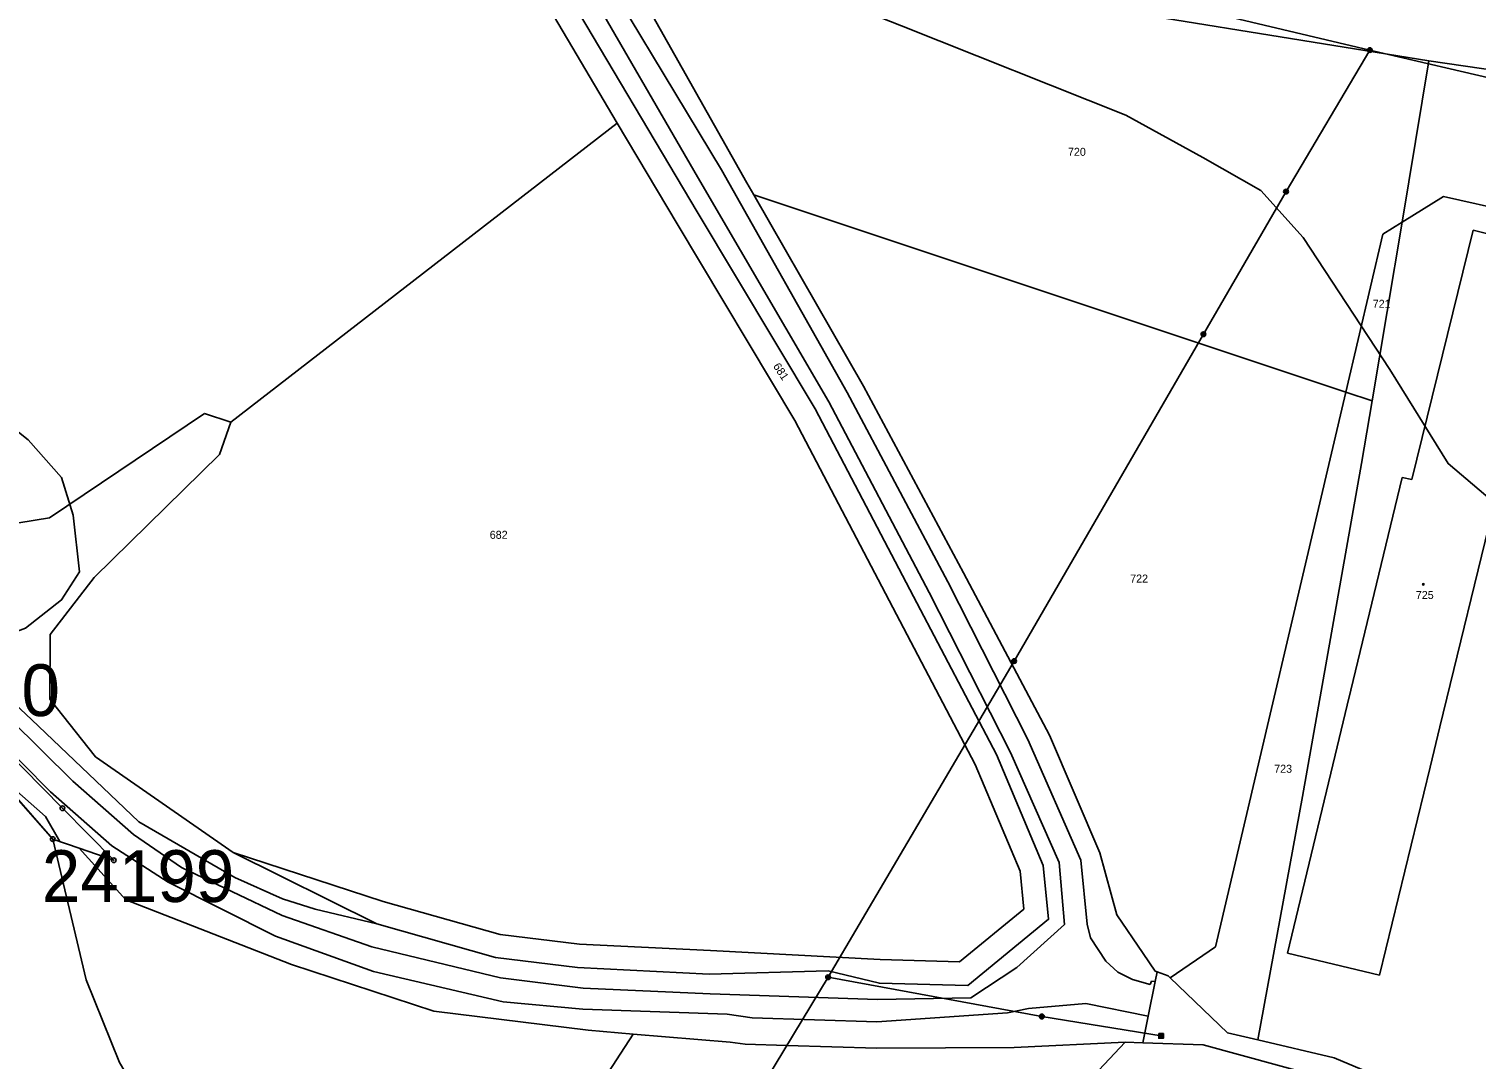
# Model space of a CAD drawing. Extents: x -725765 to -723182, y -1052705 to -1049154.
# Drawn here: x -724492.6 to -724185, y -1050781.6 to -1050562.6 of the extents above; entities that cross this region are included whole.
import ezdxf

# ---------------------------------------------------------------- set-up
doc = ezdxf.new("R2010")
doc.units = 0
for name, color, linetype in [('Vrstva 1', 7, 'Continuous'), ('Vrstva 12', 7, 'Continuous'), ('Vrstva 18', 7, 'Continuous'), ('Vrstva 19', 7, 'Continuous'), ('Vrstva 25', 7, 'Continuous'), ('Vrstva 4', 7, 'Continuous'), ('Vrstva 52', 7, 'Continuous'), ('Vrstva 53', 7, 'Continuous')]:
    doc.layers.add(name, color=color, linetype=linetype)

msp = doc.modelspace()

# ---------------------------------------------------------------- linework, layer by layer
at = {"layer": 'Vrstva 1'}
for points in [[(-724339.98, -1050595.36), (-724370.62, -1050540.98)], [(-724370.62, -1050540.98), (-724195.07, -1050569.42)], [(-724382.95, -1050556.66), (-724367.52, -1050582.69)], [(-724378.66, -1050554.1), (-724350.54, -1050601.52)], [(-724200.78, -1050603.72), (-724195.07, -1050569.42)], [(-724195.07, -1050569.42), (-724052.97, -1050590.08)], [(-724449.63, -1050646.21), (-724367.52, -1050582.69)], [(-724367.52, -1050582.69), (-724354.83, -1050604.09)], [(-724338.52, -1050597.9), (-724339.98, -1050595.36)], [(-724315.22, -1050638.57), (-724338.52, -1050597.9)], [(-724338.52, -1050597.9), (-724212.73, -1050639.81)], [(-724191.99, -1050598.25), (-724200.78, -1050603.72)], [(-724162.9, -1050604.76), (-724191.99, -1050598.25)], [(-724350.54, -1050601.52), (-724325.45, -1050643.39)], [(-724354.83, -1050604.09), (-724329.81, -1050645.84)], [(-724207.1, -1050641.69), (-724200.78, -1050603.72)], [(-724200.78, -1050603.72), (-724204.87, -1050606.26)], [(-724185.69, -1050605.4), (-724198.72, -1050658.42)], [(-724185.69, -1050605.4), (-724169.62, -1050609.35)], [(-724212.73, -1050639.81), (-724204.87, -1050606.26)], [(-724293.98, -1050678.26), (-724315.22, -1050638.57)], [(-724240.38, -1050757.73), (-724212.73, -1050639.81)], [(-724212.73, -1050639.81), (-724207.1, -1050641.69)], [(-724207.1, -1050641.69), (-724209.37, -1050655.03)], [(-724455.26, -1050644.37), (-724488.15, -1050666.54)], [(-724449.63, -1050646.21), (-724455.26, -1050644.37)], [(-724309, -1050685.58), (-724329.81, -1050645.84)], [(-724304.57, -1050683.26), (-724325.45, -1050643.39)], [(-724452.08, -1050653.05), (-724449.63, -1050646.21)], [(-724478.7, -1050679.24), (-724452.08, -1050653.05)], [(-724209.37, -1050655.03), (-724221.92, -1050725.75)], [(-724200.77, -1050657.94), (-724211.68, -1050703.14)], [(-724198.72, -1050658.42), (-724200.77, -1050657.94)], [(-724180.91, -1050662.49), (-724192.71, -1050710.97)], [(-724488.15, -1050666.54), (-724525.18, -1050672.57)], [(-724488.04, -1050691.32), (-724478.7, -1050679.24)], [(-724275.68, -1050712.73), (-724293.98, -1050678.26)], [(-724291.46, -1050718.97), (-724309, -1050685.58)], [(-724286.94, -1050716.83), (-724304.57, -1050683.26)], [(-724488.12, -1050705.1), (-724488.04, -1050691.32)], [(-724492.01, -1050709.38), (-724501.6, -1050700.47)], [(-724211.68, -1050703.14), (-724212.45, -1050706.35)], [(-724485.45, -1050728.25), (-724506.45, -1050706.93)], [(-724478.41, -1050717.32), (-724488.12, -1050705.1)], [(-724212.45, -1050706.35), (-724214.58, -1050715.2)], [(-724508.69, -1050710.74), (-724487.5, -1050734.82)], [(-724469.18, -1050731.12), (-724492.01, -1050709.38)], [(-724264.97, -1050737.72), (-724275.68, -1050712.73)], [(-724192.71, -1050710.97), (-724194.8, -1050719.52)], [(-724286.94, -1050716.83), (-724277.01, -1050740.4)], [(-724214.58, -1050715.2), (-724225.11, -1050759.05)], [(-724449.14, -1050737.68), (-724478.41, -1050717.32)], [(-724291.46, -1050718.97), (-724281.91, -1050741.65)], [(-724194.8, -1050719.52), (-724205.56, -1050763.75)], [(-724221.92, -1050725.75), (-724231.42, -1050777.49)], [(-724474.54, -1050739.32), (-724485.45, -1050728.25)], [(-724448.78, -1050742.99), (-724469.18, -1050731.12)], [(-724487.5, -1050734.82), (-724481.87, -1050736.78)], [(-724480.39, -1050764.74), (-724487.5, -1050734.82)], [(-724481.87, -1050736.78), (-724471.93, -1050747.73)], [(-724481.87, -1050736.78), (-724474.54, -1050739.32)], [(-724418.61, -1050752.86), (-724449.14, -1050737.68)], [(-724417.25, -1050748.05), (-724449.14, -1050737.68)], [(-724261.37, -1050750.9), (-724264.97, -1050737.72)], [(-724277.01, -1050740.4), (-724275.87, -1050751.85)], [(-724438.67, -1050747.5), (-724448.78, -1050742.99)], [(-724281.91, -1050741.65), (-724281.11, -1050749.68)], [(-724431.76, -1050749.69), (-724438.67, -1050747.5)], [(-724462.3, -1050751.46), (-724471.93, -1050747.73)], [(-724431.76, -1050749.69), (-724418.61, -1050752.86)], [(-724392.41, -1050755.07), (-724417.25, -1050748.05)], [(-724281.11, -1050749.68), (-724294.79, -1050760.89)], [(-724436.79, -1050761.46), (-724462.3, -1050751.46)], [(-724393.4, -1050759.99), (-724418.61, -1050752.86)], [(-724275.87, -1050751.85), (-724293.06, -1050765.94)], [(-724255.8, -1050759.1), (-724261.37, -1050750.9)], [(-724375.54, -1050757.14), (-724392.41, -1050755.07)], [(-724347.74, -1050758.5), (-724375.54, -1050757.14)], [(-724311.69, -1050760.44), (-724347.74, -1050758.5)], [(-724253.23, -1050762.89), (-724255.8, -1050759.1)], [(-724240.38, -1050757.73), (-724250.02, -1050764.28)], [(-724205.56, -1050763.75), (-724225.11, -1050759.05)], [(-724406.51, -1050771.41), (-724436.79, -1050761.46)], [(-724375.97, -1050762.12), (-724393.4, -1050759.99)], [(-724347.98, -1050763.49), (-724375.97, -1050762.12)], [(-724322.7, -1050762.83), (-724347.98, -1050763.49)], [(-724311.82, -1050765.44), (-724322.7, -1050762.83)], [(-724294.79, -1050760.89), (-724311.69, -1050760.44)], [(-724252.84, -1050763.02), (-724253.26, -1050765.11)], [(-724252.84, -1050763.02), (-724253.23, -1050762.89)], [(-724250.46, -1050763.85), (-724252.84, -1050763.02)], [(-724473.33, -1050782.28), (-724480.39, -1050764.74)], [(-724293.06, -1050765.94), (-724311.82, -1050765.44)], [(-724253.26, -1050765.11), (-724254.73, -1050772.42)], [(-724250.02, -1050764.28), (-724250.46, -1050763.85)], [(-724237.85, -1050775.98), (-724250.02, -1050764.28)], [(-724373.72, -1050775.44), (-724406.51, -1050771.41)], [(-724254.73, -1050772.42), (-724255.87, -1050778.13)], [(-724364.13, -1050776.24), (-724412.8, -1050851.2)], [(-724364.13, -1050776.24), (-724373.72, -1050775.44)], [(-724343.56, -1050777.97), (-724364.13, -1050776.24)], [(-724259.6, -1050778.01), (-724351.02, -1050875.23)], [(-724340.38, -1050778.38), (-724343.56, -1050777.97)], [(-724331.48, -1050778.65), (-724340.38, -1050778.38)], [(-724283.16, -1050779.14), (-724259.6, -1050778.01)], [(-724255.87, -1050778.13), (-724259.6, -1050778.01)], [(-724243.03, -1050778.55), (-724255.87, -1050778.13)], [(-724237.85, -1050775.98), (-724231.42, -1050777.49)], [(-724231.42, -1050777.49), (-724215.22, -1050781.29)], [(-724312.38, -1050779.23), (-724331.48, -1050778.65)], [(-724283.16, -1050779.14), (-724312.38, -1050779.23)], [(-724218.92, -1050785.13), (-724243.03, -1050778.55)], [(-724215.22, -1050781.29), (-724179.08, -1050796.55)]]:
    msp.add_lwpolyline(points, dxfattribs=at)
at = {"layer": 'Vrstva 12'}
for points in [[(-724298.9, -1050545.46), (-724207.63, -1050567.14)], [(-724207.63, -1050567.14), (-724225.43, -1050597.21)], [(-724119.84, -1050587.57), (-724207.63, -1050567.14)], [(-724225.43, -1050597.21), (-724242.98, -1050627.53)], [(-724242.98, -1050627.53), (-724283.21, -1050696.99)], [(-724322.72, -1050764.18), (-724283.21, -1050696.99)], [(-724322.72, -1050764.18), (-724352.63, -1050813.6)], [(-724277.29, -1050772.52), (-724322.72, -1050764.18)], [(-724251.97, -1050776.65), (-724277.29, -1050772.52)]]:
    msp.add_lwpolyline(points, dxfattribs=at)
at = {"layer": 'Vrstva 25'}
for points in [[(-724252.47, -1050776.15), (-724251.47, -1050776.15), (-724251.47, -1050777.15), (-724252.47, -1050777.15), (-724252.47, -1050776.15)], [(-724252.27, -1050776.35), (-724251.67, -1050776.35), (-724251.67, -1050776.95), (-724252.27, -1050776.95), (-724252.27, -1050776.35)], [(-724252.07, -1050776.55), (-724251.87, -1050776.55), (-724251.87, -1050776.75), (-724252.07, -1050776.75), (-724252.07, -1050776.55)]]:
    msp.add_lwpolyline(points, dxfattribs=at)
for centre, radius in [((-724207.63, -1050567.14), 0.5), ((-724207.63, -1050567.14), 0.3), ((-724207.63, -1050567.14), 0.15), ((-724225.43, -1050597.21), 0.5), ((-724225.43, -1050597.21), 0.3), ((-724225.43, -1050597.21), 0.15), ((-724242.98, -1050627.53), 0.5), ((-724242.98, -1050627.53), 0.3), ((-724242.98, -1050627.53), 0.15), ((-724196.24, -1050680.69), 0.175), ((-724283.21, -1050696.99), 0.5), ((-724283.21, -1050696.99), 0.3), ((-724283.21, -1050696.99), 0.15), ((-724485.45, -1050728.25), 0.5), ((-724485.45, -1050728.25), 0.032), ((-724487.5, -1050734.82), 0.5), ((-724487.5, -1050734.82), 0.032), ((-724474.54, -1050739.32), 0.5), ((-724474.54, -1050739.32), 0.032), ((-724322.72, -1050764.18), 0.5), ((-724322.72, -1050764.18), 0.3), ((-724322.72, -1050764.18), 0.15), ((-724277.29, -1050772.52), 0.5), ((-724277.29, -1050772.52), 0.3), ((-724277.29, -1050772.52), 0.15)]:
    msp.add_circle(centre, radius, dxfattribs=at)
at = {"layer": 'Vrstva 4'}
for points in [[(-724345.42, -1050592.57), (-724377.16, -1050539.79)], [(-724374.79, -1050552.08), (-724350.49, -1050594.08)], [(-724318.68, -1050639.93), (-724345.42, -1050592.57)], [(-724350.49, -1050594.08), (-724322.6, -1050641.9)], [(-724297.26, -1050680.12), (-724318.68, -1050639.93)], [(-724301.29, -1050682.41), (-724322.6, -1050641.9)], [(-724301.29, -1050682.41), (-724284, -1050716.42)], [(-724297.26, -1050680.12), (-724280.28, -1050713.67)], [(-724483.21, -1050722.53), (-724503.28, -1050702.71)], [(-724506.11, -1050706.48), (-724487.97, -1050724.77)], [(-724280.28, -1050713.67), (-724269.02, -1050739.31)], [(-724284, -1050716.42), (-724273.6, -1050739.76)], [(-724470.33, -1050733.87), (-724483.21, -1050722.53)], [(-724487.97, -1050724.77), (-724474.97, -1050736.26)], [(-724460.15, -1050740.84), (-724470.33, -1050733.87)], [(-724474.97, -1050736.26), (-724462.99, -1050743.97)], [(-724438.76, -1050751.09), (-724460.15, -1050740.84)], [(-724273.6, -1050739.76), (-724272.48, -1050752.94)], [(-724269.02, -1050739.31), (-724267.69, -1050752.93)], [(-724462.99, -1050743.97), (-724440.19, -1050755.47)], [(-724419.66, -1050757.73), (-724438.76, -1050751.09)], [(-724272.48, -1050752.94), (-724282.6, -1050762.14)], [(-724267.69, -1050752.93), (-724267, -1050755.8)], [(-724440.19, -1050755.47), (-724419.35, -1050762.98)], [(-724267, -1050755.8), (-724263.73, -1050760.74)], [(-724392.37, -1050764.29), (-724419.66, -1050757.73)], [(-724419.35, -1050762.98), (-724391.75, -1050769.39)], [(-724282.6, -1050762.14), (-724292.38, -1050768.52)], [(-724263.73, -1050760.74), (-724261.17, -1050763.09)], [(-724374.77, -1050766.52), (-724392.37, -1050764.29)], [(-724261.17, -1050763.09), (-724258.06, -1050764.69)], [(-724258.06, -1050764.69), (-724254.26, -1050765.72)], [(-724254.26, -1050765.72), (-724253.99, -1050765.01)], [(-724253.99, -1050765.01), (-724253.26, -1050765.11)], [(-724347.78, -1050767.72), (-724374.77, -1050766.52)], [(-724312.27, -1050768.88), (-724347.78, -1050767.72)], [(-724292.38, -1050768.52), (-724312.27, -1050768.88)], [(-724391.75, -1050769.39), (-724374.82, -1050770.97)], [(-724374.82, -1050770.97), (-724344.15, -1050771.99)], [(-724344.15, -1050771.99), (-724338.89, -1050772.8)], [(-724312.41, -1050773.63), (-724284.64, -1050771.73)], [(-724284.64, -1050771.73), (-724280.14, -1050770.84)], [(-724280.14, -1050770.84), (-724267.99, -1050769.77)], [(-724267.99, -1050769.77), (-724254.73, -1050772.42)], [(-724338.89, -1050772.8), (-724312.41, -1050773.63)]]:
    msp.add_lwpolyline(points, dxfattribs=at)
at = {"layer": 'Vrstva 52'}
for points in [[(-724506.66, -1050694.97), (-724493.31, -1050690), (-724485.63, -1050684), (-724481.81, -1050678), (-724483.13, -1050666), (-724485.63, -1050658), (-724492.69, -1050650), (-724527.88, -1050622), (-724562.38, -1050591), (-724598.31, -1050561), (-724618.38, -1050543), (-724647.31, -1050511), (-724667.69, -1050488), (-724701.63, -1050439), (-724731.38, -1050405), (-724752.5, -1050382), (-724783.31, -1050351), (-724814.63, -1050317)], [(-724501.6, -1050700.47), (-724492.01, -1050709.38), (-724469.18, -1050731.12), (-724448.78, -1050742.99), (-724438.67, -1050747.5), (-724431.76, -1050749.69), (-724418.61, -1050752.86), (-724393.4, -1050759.99), (-724375.97, -1050762.12), (-724347.98, -1050763.49), (-724322.7, -1050762.83), (-724311.82, -1050765.44), (-724293.06, -1050765.94), (-724275.87, -1050751.85), (-724277.01, -1050740.4), (-724286.94, -1050716.83), (-724304.57, -1050683.26), (-724325.45, -1050643.39), (-724350.54, -1050601.52), (-724378.66, -1050554.1), (-724382.04, -1050548.47), (-724395, -1050524.43), (-724396.82, -1050515.33), (-724396.8, -1050514.39)], [(-724169.81, -1050673), (-724191, -1050655), (-724203.38, -1050635), (-724221.81, -1050607), (-724230.81, -1050597), (-724243.13, -1050590), (-724259.5, -1050581), (-724307.13, -1050562), (-724339.88, -1050549), (-724371.38, -1050533), (-724377.55, -1050528.88)], [(-724370.62, -1050540.98), (-724339.98, -1050595.36), (-724338.52, -1050597.9), (-724315.22, -1050638.57), (-724293.98, -1050678.26), (-724275.68, -1050712.73), (-724264.97, -1050737.72), (-724261.37, -1050750.9), (-724255.8, -1050759.1), (-724253.23, -1050762.89), (-724252.84, -1050763.02), (-724253.26, -1050765.11), (-724254.73, -1050772.42), (-724255.87, -1050778.13), (-724259.6, -1050778.01), (-724283.16, -1050779.14), (-724312.38, -1050779.23), (-724331.48, -1050778.65), (-724340.38, -1050778.38), (-724343.56, -1050777.97), (-724364.13, -1050776.24), (-724373.72, -1050775.44), (-724406.51, -1050771.41), (-724436.79, -1050761.46), (-724462.3, -1050751.46), (-724471.93, -1050747.73), (-724481.87, -1050736.78), (-724474.54, -1050739.32), (-724485.45, -1050728.25), (-724506.45, -1050706.93)], [(-724500.75, -1050719.76), (-724487.5, -1050734.82)], [(-724487.5, -1050734.82), (-724485.97, -1050735.35), (-724489, -1050730), (-724500.75, -1050719.76)], [(-724487.5, -1050734.82), (-724480.39, -1050764.74), (-724473.33, -1050782.28), (-724459.06, -1050806.28), (-724438.42, -1050827.83)]]:
    msp.add_lwpolyline(points, dxfattribs=at)

# ---------------------------------------------------------------- texts
at = {"layer": 'Vrstva 18'}
for s, p in [('720', (-724271.76, -1050589.61)), ('721', (-724207, -1050621.91)), ('682', (-724394.63, -1050671)), ('722', (-724258.54, -1050680.3)), ('723', (-724227.94, -1050720.72))]:
    msp.add_text(s, height=1.7, dxfattribs=at).set_placement(p)
msp.add_text('681', height=1.7, rotation=303.3024, dxfattribs=at).set_placement((-724334.49, -1050634.32))
at = {"layer": 'Vrstva 19'}
msp.add_text('725', height=1.7, dxfattribs=at).set_placement((-724197.84, -1050683.79))
at = {"layer": 'Vrstva 53'}
for s, p in [('21010', (-724526.86, -1050708.67)), ('24199', (-724489.81, -1050748.18))]:
    msp.add_text(s, height=11, dxfattribs=at).set_placement(p)

doc.saveas('drawing.dxf')
